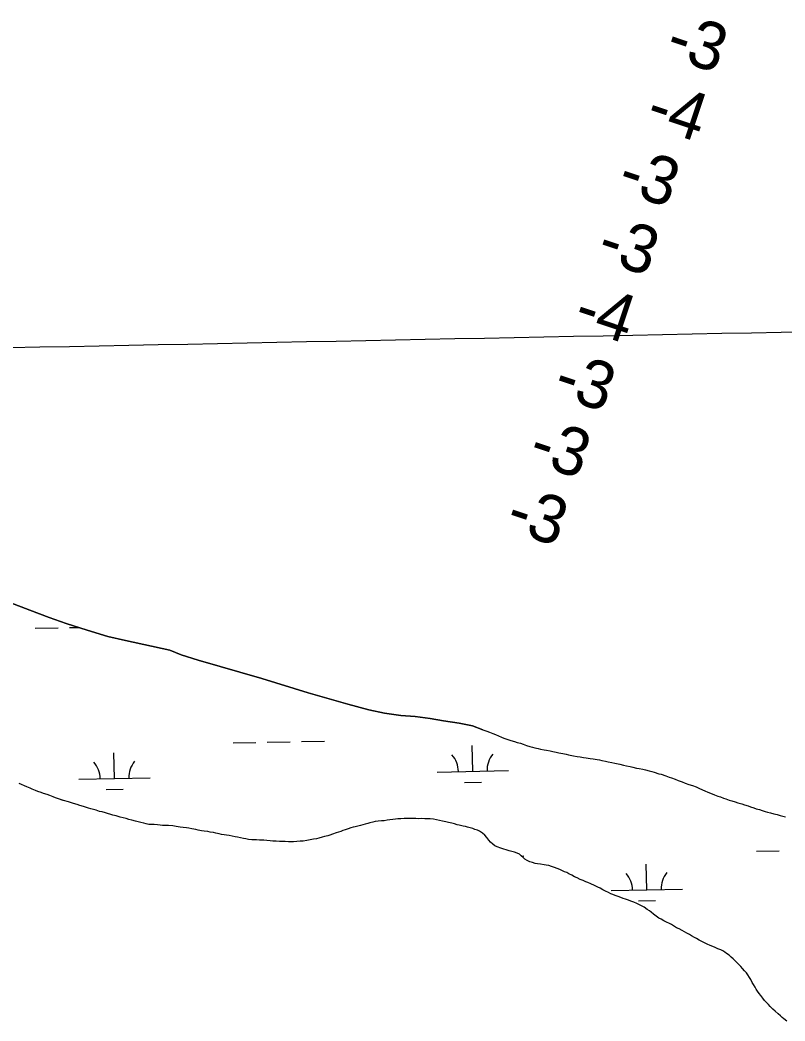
# Model space of a CAD drawing. Extents: x 3989314 to 4027622, y 243956 to 270014.
# Drawn here: x 4015281 to 4016352, y 254943 to 256346 of the extents above; entities that cross this region are included whole.
import ezdxf

# ---------------------------------------------------------------- set-up
doc = ezdxf.new("R2010")
doc.units = 0
for name, color, linetype in [('V-GRID-MAJR', 7, 'Continuous'), ('V-RIVR-EDGE', 7, 'Continuous'), ('V-RIVR-RANG', 7, 'Continuous'), ('V-WETL-SWMP', 7, 'Continuous')]:
    doc.layers.add(name, color=color, linetype=linetype)

msp = doc.modelspace()

# ---------------------------------------------------------------- linework, layer by layer
at = {"layer": 'V-GRID-MAJR'}
msp.add_spline([(3993497.6, 255455.7), (3998815.3, 255559.8), (4004133, 255664.6), (4009450.7, 255770.2), (4014768.4, 255876.5), (4020086, 255983.7), (4025403.7, 256091.6)], degree=3, dxfattribs=at)
at = {"layer": 'V-RIVR-EDGE'}
for points in [[(4015929.2, 255350.7), (4015914.6, 255356.4), (4015896.1, 255360), (4015873.9, 255363.5), (4015855.4, 255366.9), (4015834.2, 255369.4), (4015814.2, 255370.9), (4015791.5, 255374.4), (4015769.4, 255379.1), (4015740.3, 255386.7), (4015717.1, 255393.4), (4015684.7, 255402.9), (4015619.7, 255422.8), (4015530.4, 255448.6), (4015506.4, 255456), (4015490.7, 255462.5), (4015428.6, 255476), (4015403.9, 255481.7), (4015375.1, 255490.7), (4015345.4, 255499.7), (4015321.6, 255508.1), (4015294.8, 255518.5), (4015266.6, 255529.2)], [(4015929.2, 255350.7), (4015930.6, 255350.3), (4015934.8, 255348.9), (4015938.3, 255347.7), (4015943.4, 255345.6), (4015946.8, 255344.1), (4015951, 255342.4), (4015955.2, 255340.8), (4015958.7, 255339.3), (4015961.6, 255338.3), (4015965.5, 255336.9), (4015968.5, 255335.9), (4015973.4, 255334.5), (4015977.5, 255333.3), (4015982, 255332.2), (4015985.5, 255330.6), (4015990.2, 255329.1), (4015995.2, 255327.4), (4015998.8, 255326.4), (4016002, 255325.5), (4016006.5, 255324.5), (4016010.2, 255323.8), (4016014.9, 255322.8), (4016018.5, 255322.2), (4016023.3, 255321.2), (4016027.1, 255320.4), (4016031.9, 255319.5), (4016035.7, 255318.6), (4016041.2, 255317.6), (4016045.9, 255316.6), (4016049, 255315.9), (4016056.2, 255314.5), (4016061.5, 255313.5), (4016065.3, 255312.9), (4016070.2, 255312.3), (4016073.9, 255311.6), (4016079.5, 255310.7), (4016083.8, 255310.2), (4016089.5, 255309.4), (4016092.6, 255308.7), (4016096, 255307.7), (4016101.1, 255306.8), (4016104.9, 255306), (4016109.8, 255305), (4016114.1, 255304.1), (4016120.9, 255302.5), (4016126.4, 255301.3), (4016130.3, 255300.4), (4016135.4, 255299.3), (4016139.3, 255298.5), (4016144.5, 255297.2), (4016148, 255296.5), (4016153.1, 255295.5), (4016156.9, 255294.8), (4016162, 255293.5), (4016166.1, 255292.3), (4016169.1, 255291.5), (4016175.9, 255289.4), (4016178.8, 255288.5), (4016185.3, 255286.2), (4016190.1, 255284.6), (4016193.6, 255283.4), (4016198.6, 255281.5), (4016202.8, 255279.9), (4016208.4, 255278), (4016212.7, 255276.3), (4016217.8, 255274.4), (4016222.8, 255273), (4016227.8, 255271.1), (4016231.7, 255269.1), (4016236.7, 255266.7), (4016240.1, 255265.3), (4016244.5, 255263.3), (4016247.9, 255262), (4016253.6, 255259.9), (4016258.5, 255258.1), (4016262, 255256.8), (4016266.3, 255255.2), (4016269.5, 255254.1), (4016274.2, 255252.5), (4016277.9, 255251.4), (4016282.7, 255250), (4016286.6, 255248.7), (4016291.8, 255247), (4016295.7, 255245.9), (4016300.7, 255244.2), (4016304.2, 255243), (4016308.8, 255241.4), (4016312.3, 255240.3), (4016316.9, 255239.1), (4016320.4, 255237.9), (4016324.8, 255236.6), (4016328.1, 255235.6), (4016332.1, 255234.6), (4016336.7, 255233.3), (4016341.5, 255232), (4016345.9, 255230.7), (4016349.2, 255230), (4016353.1, 255229.1)], [(4015538.8, 255208.9), (4015535.3, 255209.4), (4015530.5, 255210.3), (4015527, 255211.1), (4015521.5, 255212.2), (4015517.2, 255212.9), (4015513.9, 255213.5), (4015509.4, 255214), (4015505.3, 255214.5), (4015499.5, 255215.5), (4015494.8, 255216.1), (4015488.9, 255216.6), (4015484.9, 255216.7), (4015480.3, 255217), (4015477.2, 255217.2), (4015473.6, 255217.5), (4015468.8, 255218), (4015464.7, 255218.3), (4015461.5, 255218.3), (4015457.6, 255219.2), (4015454.3, 255220), (4015450.3, 255220.9), (4015446.3, 255221.9), (4015442.6, 255222.8), (4015437.6, 255224.1), (4015433.2, 255225.4), (4015429.4, 255226.4), (4015425.2, 255227.7), (4015421.1, 255228.6), (4015415.5, 255230.1), (4015411, 255231.2), (4015407.9, 255232.1), (4015403.6, 255233.4), (4015400.5, 255234.3), (4015395.8, 255235.7), (4015392.3, 255236.6), (4015387.4, 255238.2), (4015384, 255239.1), (4015379.9, 255240.3), (4015376.7, 255241.2), (4015372.7, 255242.4), (4015369.6, 255243.4), (4015364.9, 255244.8), (4015361.1, 255246), (4015355.8, 255247.7), (4015351.6, 255248.9), (4015348.6, 255249.8), (4015341.5, 255252), (4015334.9, 255254.2), (4015330.5, 255255.7), (4015327.2, 255256.9), (4015322.8, 255258.6), (4015318.9, 255260), (4015313.9, 255261.8), (4015310.3, 255262.9), (4015305.8, 255264.5), (4015302.6, 255265.8), (4015298.1, 255267.6), (4015294.9, 255269.1), (4015290.6, 255270.8), (4015287.3, 255272.3), (4015283.1, 255274.1), (4015279.5, 255275.7)], [(4015928.7, 255206), (4015924.5, 255208.8), (4015921.7, 255210.2), (4015918.1, 255211.3), (4015915.3, 255212.5), (4015911.6, 255213.4), (4015907.7, 255214.4), (4015904.7, 255215.2), (4015901.5, 255215.9), (4015896.2, 255217.2), (4015893.1, 255217.8), (4015889.3, 255219), (4015885.7, 255219.9), (4015880.9, 255221), (4015877.5, 255221.9), (4015872.8, 255223), (4015868.7, 255223.9), (4015864.2, 255224.9), (4015860, 255225.5), (4015855.3, 255226), (4015852.2, 255226), (4015847.9, 255226.2), (4015843.1, 255226.5), (4015838.8, 255226.3), (4015835.4, 255226.4), (4015831, 255226.5), (4015827.9, 255226.5), (4015823.7, 255226.8), (4015818.9, 255226.5), (4015814.5, 255226.2), (4015810.2, 255225.9), (4015807, 255225.7), (4015803, 255225.2), (4015798.7, 255224.7), (4015795.1, 255224.2), (4015790.8, 255223.5), (4015787.4, 255223.2), (4015782.8, 255222.8), (4015778.5, 255222.3), (4015774.9, 255221.6), (4015770.9, 255220.5), (4015767.9, 255219.7), (4015764.2, 255218.8), (4015761, 255217.9), (4015757.7, 255217), (4015754.1, 255216), (4015750.5, 255215), (4015747.5, 255214.3), (4015744.1, 255213.3), (4015740.5, 255211.9), (4015736.4, 255210.5), (4015733.3, 255209.6), (4015730.4, 255208.6), (4015727.1, 255207.4), (4015723.7, 255206.3), (4015718.4, 255204.5), (4015714.8, 255203.4), (4015711.9, 255202.4), (4015707.6, 255201.2), (4015704.2, 255200.3), (4015699.6, 255199.1), (4015696, 255198.3), (4015692, 255197.4), (4015687.4, 255196.5), (4015682.7, 255195.8), (4015677.7, 255195), (4015673.5, 255194.6), (4015668.5, 255194.3), (4015663.9, 255194), (4015660.1, 255194), (4015657, 255194), (4015652.5, 255194.2), (4015648.8, 255194.3), (4015644.2, 255194.3), (4015639.5, 255194.7), (4015635.1, 255194.9), (4015631.4, 255195.3), (4015626.8, 255195.7), (4015622.6, 255196.2), (4015619.5, 255196.4), (4015616.2, 255196.4), (4015612.3, 255196.5), (4015608.8, 255196.5), (4015605.5, 255196.5), (4015601, 255197.1), (4015597.2, 255198), (4015594.1, 255198.6), (4015589.6, 255199.5), (4015585.5, 255200.3), (4015582.2, 255200.9), (4015577.9, 255201.8), (4015573.7, 255202.6), (4015570, 255203.2), (4015566.8, 255203.7), (4015562.9, 255204.4), (4015559.8, 255205.1), (4015555.4, 255206.1), (4015552, 255206.8), (4015547.3, 255207.5), (4015543.8, 255208.2), (4015538.8, 255208.9)], [(4016282.6, 255027.2), (4016279.8, 255030.1), (4016277.2, 255032.2), (4016274.1, 255034.9), (4016270.7, 255037.5), (4016268.2, 255039.3), (4016265.3, 255041), (4016262.6, 255042.4), (4016258.5, 255043.9), (4016254.5, 255045.7), (4016251.5, 255047), (4016247.6, 255048.8), (4016243.3, 255050.6), (4016238.8, 255052.8), (4016235, 255054.8), (4016232.2, 255056.2), (4016228.4, 255058.2), (4016225.6, 255059.8), (4016221.7, 255062), (4016218.7, 255063.8), (4016214.8, 255066), (4016211.9, 255067.7), (4016208.3, 255069.6), (4016204.1, 255071.8), (4016200.6, 255073.5), (4016197.7, 255075.3), (4016193.5, 255077.9), (4016190.7, 255079.4), (4016186.5, 255081.3), (4016182.6, 255083.4), (4016178.9, 255085.3), (4016175.9, 255087), (4016172.1, 255089.7), (4016168.2, 255092.6), (4016165.1, 255095.2), (4016162.5, 255097.1), (4016159.2, 255099.3), (4016155.3, 255102.2), (4016151.6, 255104.2), (4016147.7, 255106.3), (4016144.7, 255107.7), (4016140.7, 255109.4), (4016136.4, 255110.9), (4016133.2, 255112.1), (4016129.2, 255113.5), (4016125.6, 255114.7), (4016122.4, 255115.9), (4016118.6, 255117.4), (4016114.7, 255118.8), (4016111.2, 255119.9), (4016108.5, 255121.2), (4016105.1, 255122.8), (4016101, 255124.8), (4016097.4, 255126.8), (4016093.5, 255128.8), (4016090.1, 255130.5), (4016085.6, 255132.6), (4016080.6, 255134.9), (4016076.4, 255136.7), (4016073.5, 255138), (4016069.9, 255139.6), (4016065.4, 255141.3), (4016061.1, 255143.4), (4016057.6, 255144.9), (4016053.7, 255147.3), (4016049.8, 255149.2), (4016046.9, 255150.9), (4016043.8, 255152), (4016040, 255153.6), (4016037, 255155), (4016033.2, 255156.4), (4016029.4, 255157.9), (4016025.2, 255159.2), (4016021.5, 255160.5), (4016018.1, 255161.3), (4016015, 255161.7), (4016010, 255162.5), (4016005.8, 255163.2), (4016002.4, 255163.7), (4015998.8, 255164.7), (4015995, 255165.9), (4015991.4, 255167.7), (4015988.2, 255169.7), (4015985.9, 255171.9), (4015983.1, 255174.4), (4015980.4, 255176.7), (4015977.3, 255178), (4015973.7, 255179.2), (4015969.7, 255180.3), (4015965.9, 255181.3), (4015962, 255182.5), (4015958.6, 255183.7), (4015954.2, 255185.1), (4015949.5, 255186.7), (4015946.2, 255188.4), (4015943, 255190.7), (4015940.1, 255193.3), (4015937.5, 255196.3), (4015934.9, 255199.9), (4015932.1, 255203.1), (4015928.7, 255206)], [(4016354.8, 254942.8), (4016351, 254945.8), (4016348.4, 254947.9), (4016346.2, 254950), (4016342.9, 254952.8), (4016338.6, 254956.7), (4016335.6, 254959.5), (4016331.8, 254963.3), (4016329.3, 254965.8), (4016325.9, 254969.3), (4016323.8, 254971.7), (4016321.2, 254974.8), (4016318.4, 254978.6), (4016316.2, 254981.3), (4016314.1, 254984.8), (4016312.3, 254987.4), (4016310.7, 254990.1), (4016308.4, 254993.9), (4016306.6, 254996.9), (4016304.5, 255000.9), (4016302.6, 255004), (4016300.2, 255007.7), (4016298.3, 255010.1), (4016295.9, 255013.3), (4016293.1, 255016.4), (4016290.4, 255019.2), (4016287.8, 255022.1), (4016285.6, 255024.4), (4016282.6, 255027.2)]]:
    msp.add_lwpolyline(points, dxfattribs=at)
at = {"layer": 'V-WETL-SWMP'}
for p, q in [((4015302.2, 255493.2), (4015334.2, 255493.8)), ((4015350.2, 255494.1), (4015363.1, 255494.4)), ((4015579.3, 255332.5), (4015611.3, 255333.1)), ((4015627.3, 255333.4), (4015659.3, 255334.1)), ((4015675.3, 255334.4), (4015707.3, 255335)), ((4015915, 255292.7), (4015914.3, 255328.7)), ((4015413.2, 255282.7), (4015412.5, 255318.7)), ((4015363.2, 255281.7), (4015463.2, 255283.7)), ((4015865.1, 255291.7), (4015965, 255293.7)), ((4015401.5, 255267.1), (4015425.5, 255267.5)), ((4015903.4, 255277.1), (4015927.4, 255277.5)), ((4015983.6, 255174), (4015986.6, 255174.1)), ((4016312.4, 255180.6), (4016344.4, 255181.2)), ((4016158.9, 255126.7), (4016158.2, 255162.7)), ((4016108.9, 255125.7), (4016208.9, 255127.7)), ((4016147.2, 255111.1), (4016171.2, 255111.6))]:
    msp.add_line(p, q, dxfattribs=at)
for points in [[(4015266.6, 255529.2), (4015294.8, 255518.5), (4015321.6, 255508.1), (4015345.4, 255499.7), (4015375.1, 255490.7), (4015403.9, 255481.7), (4015428.6, 255476), (4015490.7, 255462.5), (4015506.4, 255456), (4015530.4, 255448.6), (4015619.7, 255422.8), (4015684.7, 255402.9), (4015717.1, 255393.4), (4015740.3, 255386.7), (4015769.4, 255379.1), (4015791.5, 255374.4), (4015814.2, 255370.9), (4015834.2, 255369.4), (4015855.4, 255366.9), (4015873.9, 255363.5), (4015896.1, 255360), (4015914.6, 255356.4), (4015929.2, 255350.7), (4015930.6, 255350.3), (4015934.8, 255348.9), (4015938.3, 255347.7), (4015943.4, 255345.6), (4015946.8, 255344.1), (4015951, 255342.4), (4015955.2, 255340.8), (4015958.7, 255339.3), (4015961.6, 255338.3), (4015965.5, 255336.9), (4015968.5, 255335.9), (4015973.4, 255334.5), (4015977.5, 255333.3), (4015982, 255332.2), (4015985.5, 255330.6), (4015990.2, 255329.1), (4015995.2, 255327.4), (4015998.8, 255326.4), (4016002, 255325.5), (4016006.5, 255324.5), (4016010.2, 255323.8)], [(4016010.2, 255323.8), (4016014.9, 255322.8), (4016018.5, 255322.2), (4016023.3, 255321.2), (4016027.1, 255320.4), (4016031.9, 255319.5), (4016035.7, 255318.6), (4016041.2, 255317.6), (4016045.9, 255316.6), (4016049, 255315.9), (4016056.2, 255314.5), (4016061.5, 255313.5), (4016065.3, 255312.9), (4016070.2, 255312.3), (4016073.9, 255311.6), (4016079.5, 255310.7), (4016083.8, 255310.2), (4016089.5, 255309.4), (4016092.6, 255308.7), (4016096, 255307.7), (4016101.1, 255306.8), (4016104.9, 255306), (4016109.8, 255305), (4016114.1, 255304.1), (4016120.9, 255302.5), (4016126.4, 255301.3), (4016130.3, 255300.4), (4016135.4, 255299.3), (4016139.3, 255298.5), (4016144.5, 255297.2), (4016148, 255296.5), (4016153.1, 255295.5), (4016156.9, 255294.8), (4016162, 255293.5), (4016166.1, 255292.3), (4016169.1, 255291.5), (4016175.9, 255289.4), (4016178.8, 255288.5), (4016185.3, 255286.2), (4016190.1, 255284.6), (4016193.6, 255283.4), (4016198.6, 255281.5), (4016202.8, 255279.9), (4016208.4, 255278), (4016212.7, 255276.3), (4016217.8, 255274.4), (4016222.8, 255273), (4016227.8, 255271.1), (4016231.7, 255269.1), (4016236.7, 255266.7), (4016240.1, 255265.3), (4016244.5, 255263.3), (4016247.9, 255262), (4016253.6, 255259.9), (4016258.5, 255258.1), (4016262, 255256.8), (4016266.3, 255255.2), (4016269.5, 255254.1), (4016274.2, 255252.5), (4016277.9, 255251.4), (4016282.7, 255250), (4016286.6, 255248.7), (4016291.8, 255247), (4016295.7, 255245.9), (4016300.7, 255244.2), (4016304.2, 255243), (4016308.8, 255241.4), (4016312.3, 255240.3), (4016316.9, 255239.1), (4016320.4, 255237.9), (4016324.8, 255236.6), (4016328.1, 255235.6), (4016332.1, 255234.6), (4016336.7, 255233.3), (4016341.5, 255232), (4016345.9, 255230.7), (4016349.2, 255230), (4016353.1, 255229.1)], [(4015538.8, 255208.9), (4015535.3, 255209.4), (4015530.5, 255210.3), (4015527, 255211.1), (4015521.5, 255212.2), (4015517.2, 255212.9), (4015513.9, 255213.5), (4015509.4, 255214), (4015505.3, 255214.5), (4015499.5, 255215.5), (4015494.8, 255216.1), (4015488.9, 255216.6), (4015484.9, 255216.7), (4015480.3, 255217), (4015477.2, 255217.2), (4015473.6, 255217.5), (4015468.8, 255218), (4015464.7, 255218.3), (4015461.5, 255218.3), (4015457.6, 255219.2), (4015454.3, 255220), (4015450.3, 255220.9), (4015446.3, 255221.9), (4015442.6, 255222.8), (4015437.6, 255224.1), (4015433.2, 255225.4), (4015429.4, 255226.4), (4015425.2, 255227.7), (4015421.1, 255228.6), (4015415.5, 255230.1), (4015411, 255231.2), (4015407.9, 255232.1), (4015403.6, 255233.4), (4015400.5, 255234.3), (4015395.8, 255235.7), (4015392.3, 255236.6), (4015387.4, 255238.2), (4015384, 255239.1), (4015379.9, 255240.3), (4015376.7, 255241.2), (4015372.7, 255242.4), (4015369.6, 255243.4), (4015364.9, 255244.8), (4015361.1, 255246), (4015355.8, 255247.7), (4015351.6, 255248.9), (4015348.6, 255249.8), (4015341.6, 255252), (4015334.9, 255254.2), (4015330.5, 255255.7), (4015327.2, 255256.9), (4015322.8, 255258.6), (4015318.9, 255260), (4015313.9, 255261.8), (4015310.3, 255262.9), (4015305.8, 255264.5), (4015302.6, 255265.8), (4015298.1, 255267.6), (4015294.9, 255269.1), (4015290.6, 255270.8), (4015287.3, 255272.3), (4015283.1, 255274.1), (4015279.5, 255275.7)], [(4015928.7, 255206), (4015924.5, 255208.8), (4015921.7, 255210.2), (4015918.1, 255211.3), (4015915.3, 255212.5), (4015911.6, 255213.4), (4015907.7, 255214.4), (4015904.7, 255215.2), (4015901.5, 255215.9), (4015896.2, 255217.2), (4015893.1, 255217.8), (4015889.3, 255219), (4015885.7, 255219.9), (4015880.9, 255221), (4015877.5, 255221.9), (4015872.8, 255223), (4015868.7, 255223.9), (4015864.2, 255224.9), (4015860, 255225.5), (4015855.3, 255226), (4015852.2, 255226), (4015847.9, 255226.2), (4015843.1, 255226.5), (4015838.8, 255226.3), (4015835.4, 255226.4), (4015831, 255226.5), (4015827.9, 255226.5), (4015823.7, 255226.8), (4015818.9, 255226.5), (4015814.5, 255226.2), (4015810.2, 255225.9), (4015807, 255225.7), (4015803, 255225.2), (4015798.7, 255224.7), (4015795.1, 255224.2), (4015790.8, 255223.5), (4015787.4, 255223.2), (4015782.8, 255222.8), (4015778.5, 255222.3), (4015774.9, 255221.6), (4015770.9, 255220.5), (4015767.9, 255219.7), (4015764.2, 255218.8), (4015761, 255217.9), (4015757.7, 255217), (4015754.1, 255216), (4015750.5, 255215), (4015747.5, 255214.3), (4015744.1, 255213.3), (4015740.5, 255211.9), (4015736.4, 255210.5), (4015733.3, 255209.6), (4015730.4, 255208.6), (4015727.1, 255207.5), (4015723.7, 255206.3), (4015718.4, 255204.5), (4015714.8, 255203.4), (4015711.9, 255202.4), (4015707.6, 255201.2), (4015704.2, 255200.3), (4015699.6, 255199.1), (4015696, 255198.3), (4015692, 255197.4), (4015687.4, 255196.5), (4015682.7, 255195.8), (4015677.7, 255195), (4015673.5, 255194.6), (4015668.5, 255194.3), (4015663.9, 255194), (4015660.1, 255194), (4015657, 255194), (4015652.5, 255194.2), (4015648.8, 255194.3), (4015644.2, 255194.3), (4015639.5, 255194.7), (4015635.1, 255194.9), (4015631.4, 255195.3), (4015626.8, 255195.7), (4015622.6, 255196.2), (4015619.5, 255196.4), (4015616.2, 255196.4), (4015612.3, 255196.5), (4015608.8, 255196.5), (4015605.5, 255196.5), (4015601, 255197.1), (4015597.2, 255198), (4015594.1, 255198.6), (4015589.6, 255199.5), (4015585.5, 255200.3), (4015582.2, 255200.9), (4015577.9, 255201.8), (4015573.7, 255202.6), (4015570, 255203.2), (4015566.8, 255203.7), (4015562.9, 255204.4), (4015559.8, 255205.1), (4015555.4, 255206.1), (4015552, 255206.8), (4015547.3, 255207.5), (4015543.8, 255208.2), (4015538.8, 255208.9)], [(4016005.8, 255163.2), (4016002.4, 255163.7), (4015998.8, 255164.7), (4015995, 255165.9), (4015991.4, 255167.7), (4015988.2, 255169.7), (4015985.9, 255171.9), (4015983.1, 255174.4), (4015980.4, 255176.7), (4015977.3, 255178), (4015973.7, 255179.2), (4015969.7, 255180.3), (4015965.9, 255181.3), (4015962, 255182.5), (4015958.6, 255183.7), (4015954.2, 255185.1), (4015949.5, 255186.7), (4015946.2, 255188.4), (4015943, 255190.7), (4015940.1, 255193.3), (4015937.5, 255196.3), (4015934.9, 255199.9), (4015932.1, 255203.1), (4015928.7, 255206)], [(4016338.6, 254956.7), (4016335.6, 254959.5), (4016331.8, 254963.3), (4016329.3, 254965.8), (4016325.9, 254969.3), (4016323.8, 254971.7), (4016321.2, 254974.8), (4016318.4, 254978.6), (4016316.2, 254981.3), (4016314.1, 254984.8), (4016312.3, 254987.4), (4016310.7, 254990.1), (4016308.4, 254993.9), (4016306.6, 254996.9), (4016304.5, 255000.9), (4016302.6, 255004), (4016300.2, 255007.7), (4016298.3, 255010.1), (4016295.9, 255013.3), (4016293.1, 255016.4), (4016290.4, 255019.2), (4016287.8, 255022.1), (4016285.6, 255024.4), (4016282.6, 255027.2), (4016279.8, 255030.1), (4016277.2, 255032.2), (4016274.1, 255034.9), (4016270.7, 255037.5), (4016268.2, 255039.3), (4016265.3, 255041), (4016262.6, 255042.4), (4016258.5, 255043.9), (4016254.5, 255045.7), (4016251.5, 255047), (4016247.6, 255048.8), (4016243.3, 255050.6), (4016238.8, 255052.8), (4016235, 255054.8), (4016232.2, 255056.2), (4016228.4, 255058.2), (4016225.6, 255059.8), (4016221.7, 255062), (4016218.7, 255063.8), (4016214.8, 255066), (4016211.9, 255067.7), (4016208.3, 255069.6), (4016204.1, 255071.8), (4016200.6, 255073.5), (4016197.7, 255075.3), (4016193.5, 255077.9), (4016190.7, 255079.4), (4016186.5, 255081.3), (4016182.6, 255083.4), (4016178.9, 255085.3), (4016175.9, 255087), (4016172.1, 255089.7), (4016168.2, 255092.6), (4016165.1, 255095.2), (4016162.5, 255097.1), (4016159.2, 255099.3), (4016155.3, 255102.2), (4016151.6, 255104.2), (4016147.7, 255106.3), (4016144.7, 255107.7), (4016140.7, 255109.4), (4016136.4, 255110.9), (4016133.2, 255112.1), (4016129.2, 255113.5), (4016125.6, 255114.7), (4016122.4, 255115.9), (4016118.6, 255117.4), (4016114.7, 255118.8), (4016111.2, 255119.9), (4016108.5, 255121.2), (4016105.1, 255122.8), (4016101, 255124.8), (4016097.4, 255126.8), (4016093.5, 255128.8), (4016090.1, 255130.5), (4016085.6, 255132.6), (4016080.6, 255134.9), (4016076.4, 255136.7), (4016073.5, 255138), (4016069.9, 255139.6), (4016065.4, 255141.3), (4016061.1, 255143.4), (4016057.6, 255144.9), (4016053.7, 255147.3), (4016049.8, 255149.2), (4016046.9, 255150.9), (4016043.8, 255152), (4016040, 255153.6), (4016037, 255155), (4016033.2, 255156.4), (4016029.4, 255157.9), (4016025.2, 255159.2), (4016021.5, 255160.5), (4016018.1, 255161.3), (4016015, 255161.7), (4016010, 255162.5), (4016005.8, 255163.2)], [(4016354.8, 254942.8), (4016351, 254945.8), (4016348.4, 254947.9), (4016346.2, 254950), (4016342.9, 254952.8), (4016338.6, 254956.7)]]:
    msp.add_lwpolyline(points, dxfattribs=at)
for centre, start, end in [((4015859.8, 255292.1), 0.3699, 41.9135), ((4015970.3, 255294.3), 140.3699, 181.9135), ((4015358, 255282.1), 0.3699, 41.9135), ((4015468.5, 255284.3), 140.3699, 181.9135), ((4016103.6, 255126.1), 0.3699, 41.9135), ((4016214.1, 255128.3), 140.3699, 181.9135)]:
    msp.add_arc(centre, 35.2, start, end, dxfattribs=at)

# ---------------------------------------------------------------- texts
at = {"layer": 'V-RIVR-RANG'}
for s, p in [('-3', (4016182.1, 256295.6)), ('-4', (4016154.4, 256199.4)), ('-3', (4016115, 256107.3)), ('-3', (4016086.1, 256011.2)), ('-4', (4016053.4, 255916.8)), ('-3', (4016025.1, 255820.8)), ('-3', (4015990.3, 255727.2)), ('-3', (4015958.3, 255632.5))]:
    msp.add_text(s, height=67, rotation=341.535, dxfattribs=at).set_placement(p)

doc.saveas('drawing.dxf')
